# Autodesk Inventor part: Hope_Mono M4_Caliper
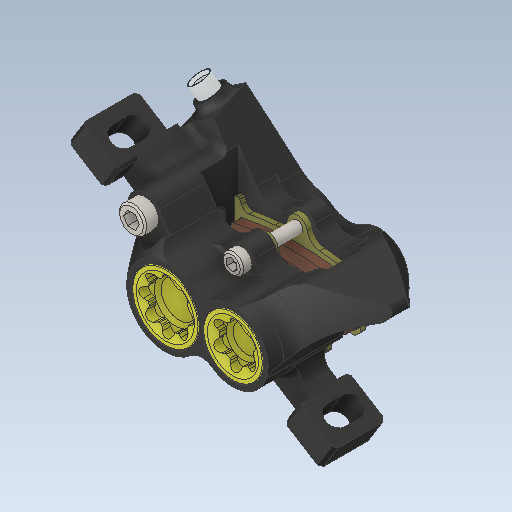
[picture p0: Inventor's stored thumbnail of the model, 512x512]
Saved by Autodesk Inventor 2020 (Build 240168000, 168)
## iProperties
Created: 2007-02
Part Number: Hope_Mono M4_Caliper
Material: Ogólny
Document SubType Name: Modeling
Designer: Tomasz
Density: 1 g/cm^3
Appearance: Domyślna
Sending System: SolidWorks 2017
Last Author: Tomasz
Last Saved: 2017-11-19
Author: Tomasz
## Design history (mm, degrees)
feature "Imported1"
feature "Imported2"
feature "Imported3"
feature "Imported4"
feature "Imported5"
feature "Chanfrein1" [Imported]
feature "Chanfrein2" [Imported]
feature "Chanfrein3" [Imported]
node "Bryła1"
node "Bryła2"
node "Bryła3"
node "Bryła4"
node "Bryła5"
node "Bryła6"
node "Bryła7"
node "Bryła8"
